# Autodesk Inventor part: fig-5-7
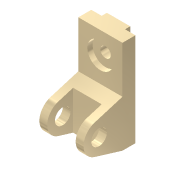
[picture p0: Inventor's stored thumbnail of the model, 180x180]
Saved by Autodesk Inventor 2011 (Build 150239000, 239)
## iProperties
Shininess: 65.0
Angle Display Precision: 2
Document Length Units: 11269
Document Angle Units: 11279
Document Time Units: 11290
Document Mass Units: 11283
Document Length Units Precision: 3
Document Angle Units Precision: 2
Compacted: False
Created: 2001-11
Part Number: fig-5-7
Document SubType Name: Modeling
Designer: Renu Muthoo
Density: 1 g/cm^3
Density: 0.0
Volumn: 0.0
Area: 0.0
PropertySet Name: Model Information
Control State: 0
Master: False
Checked Out: False
Author: Renu Muthoo
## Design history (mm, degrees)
node "Sketch1"
sketch "Sketch2"
  geometry: L1 (33.257, 104.664)-(33.257, -75.336); L2 (33.257, -75.336)-(8.257, -75.336); L3 (8.257, -75.336)-(-45.451, -59.045); L4 (-45.451, -1.628)-(8.257, 14.664); L5 (8.257, 14.664)-(8.257, 104.664); L6 (8.257, 104.664)-(33.257, 104.664); C1 r 15 at (-36.743, -30.336); A1 r 30 centre (-36.743, -30.336) between (-45.451, -1.628) and (-45.451, -59.045)
  constraints: 12 end point, 2 centre point, 2 equal length, 2 parallel, 2 point on circle, 2 tangent, 1 coincident, 1 perpendicular, 1 vertical
  dimensions: "d0" = 180 distance of L1.start L1.end; "d1" = 30 radius of A1; "d2" = 25 distance of L5.end L1.start; "d3" = 45 distance from line of L2 A1.centre; "d4" = 70 distance from line of L1 A1.centre; "d5" = 30 diameter of C1
extrude "Extrusion1" new body sketch "Sketch2" distance "d6" = 85; taper "d7" = 0 deg
workplane "Work Plane1"
sketch "Sketch3"
  geometry: L1 (15, 62.364)-(70, 62.364); L2 (70, 62.364)-(70, -52.386); L3 (70, -52.386)-(15, -52.386); L4 (15, -52.386)-(15, 62.364); L5 (0, -45)-(0, -28.708) reference
  constraints: 8 end point, 2 parallel, 1 horizontal, 1 perpendicular
  dimensions: "d8" = 55 distance of L1.start L1.end; "d9" = 15 distance between parallel lines of L5 L4
extrude "Extrusion2" cut sketch "Sketch3" distance "d10" = 50; taper "d11" = 0 deg
sketch "Sketch4"
  geometry: L1 (0, 25)-(85, 25) reference; L2 (0, 0)-(0, 25) reference; L3 (20, 25)-(65, 25); L4 (65, 25)-(65, 35); L5 (65, 35)-(20, 35); L6 (20, 35)-(20, 25)
  constraints: 8 end point, 2 parallel, 1 horizontal, 1 perpendicular, 1 point on line
  dimensions: "d12" = 45 distance of L4.end L5.end; "d13" = 10 distance of L3.end L4.end; "d14" = 20 distance between parallel lines of L2 L6
extrude "Extrusion3" join sketch "Sketch4" stored distance "d15" = 50; taper "d16" = 0 deg
sketch "Sketch5"
  geometry: L1 (85, 0)-(85, 90) reference; L2 (0, 90)-(85, 90) reference; 1 further point
  dimensions: "d17" = 42 distance from line of L2 point (42.5, 48); "d18" = 42.5 distance from line of L1 point (42.5, 48)
hole "Hole1" sketch "Sketch5" at (42.5, 48) diameter "d19" = 20; stored, may be unused: countersink angle "d23" = 82 deg, drill point angle "d25" = 118 deg; dims "d20" = 6, "d21" = 50, "d22" = 10, "d24" = 8
body "Solid1"
